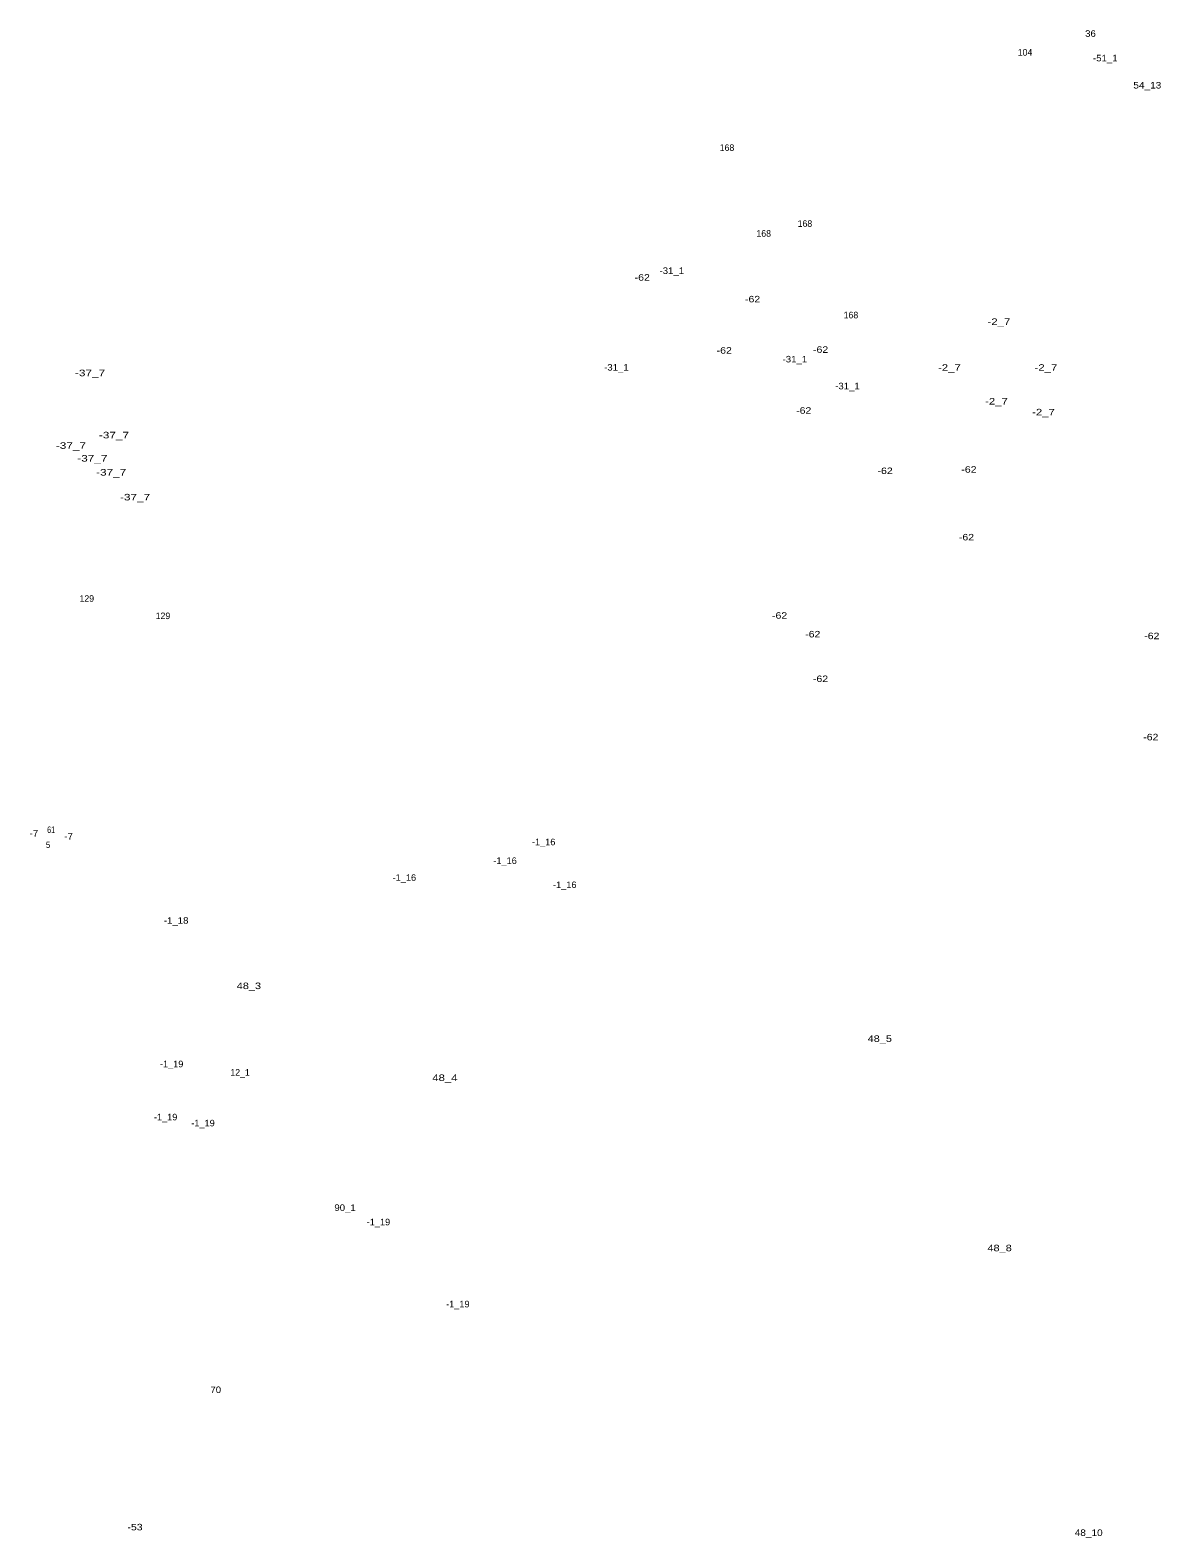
# Model space of a CAD drawing. Extents: x -660405 to -657848, y -988475 to -986360.
# Drawn here: x -659668 to -658976, y -987283 to -986360 of the extents above; entities that cross this region are included whole.
import ezdxf
from ezdxf.enums import TextEntityAlignment as Align

# ---------------------------------------------------------------- set-up
doc = ezdxf.new("R2010")
doc.units = 0
doc.header["$LTSCALE"] = 1.6
doc.layers.add('24', color=7, linetype='Continuous')

msp = doc.modelspace()

# ---------------------------------------------------------------- texts
at = {"layer": '24'}
for s, width, p in [('36', 1.1, (-659019.41, -986364.08)), ('-51_1', 1.1, (-659010.34, -986379.12)), ('54_13', 1.15, (-658984.63, -986395.73)), ('-31_1', 1.1, (-659275.63, -986509.19)), ('-62', 1.2, (-659293.71, -986513.31)), ('-62', 1.2, (-659226.19, -986526.6)), ('-2_7', 1.3, (-659075.46, -986540.37)), ('-62', 1.2, (-659243.53, -986557.97)), ('-31_1', 1.1, (-659200.319, -986563.32)), ('-62', 1.2, (-659184.57, -986557.46)), ('-37_7', 1.35, (-659631.64, -986571.75)), ('-31_1', 1.1, (-659309.54, -986568.33)), ('-2_7', 1.3, (-659105.72, -986568.42)), ('-2_7', 1.3, (-659046.68, -986568.42)), ('-31_1', 1.1, (-659168.14, -986579.77)), ('-2_7', 1.3, (-659076.94, -986589.09)), ('-62', 1.2, (-659194.9, -986594.73)), ('-2_7', 1.3, (-659048.16, -986595.73)), ('-37_7', 1.35, (-659617.02, -986609.78)), ('-37_7', 1.35, (-659643.341, -986616.18)), ('-37_7', 1.35, (-659630.231, -986623.99)), ('-62', 1.2, (-659093.8, -986630.81)), ('-37_7', 1.35, (-659618.721, -986632.58)), ('-62', 1.2, (-659145.09, -986631.64)), ('-37_7', 1.35, (-659604.091, -986647.76)), ('-62', 1.2, (-659095.28, -986672.24)), ('-62', 1.2, (-659209.66, -986720.15)), ('-62', 1.2, (-659189.36, -986731.59)), ('-62', 1.2, (-658981.87, -986732.66)), ('-62', 1.2, (-659184.6, -986758.9)), ('-62', 1.2, (-658982.48, -986794.56)), ('61', 0.8, (-659655.471, -986851.26)), ('-7', 1.1, (-659665.951, -986853.4)), ('5', 0.9, (-659657.329, -986860.48)), ('-7', 1.1, (-659644.74, -986855.25)), ('-1_16', 1.05, (-659354.061, -986858.74)), ('-1_16', 1.05, (-659377.671, -986870.18)), ('-1_16', 1.05, (-659439.291, -986880.51)), ('-1_16', 1.05, (-659341.14, -986884.94)), ('-1_18', 1.1, (-659578.959, -986906.75)), ('48_3', 1.25, (-659534.441, -986946.76)), ('48_5', 1.25, (-659148.361, -986979.08)), ('-1_19', 1.05, (-659581.721, -986994.58)), ('48_4', 1.3, (-659414.481, -987002.99)), ('-1_19', 1.05, (-659585.41, -987027.06)), ('-1_19', 1.05, (-659562.53, -987030.75)), ('90_1', 1.1, (-659475.59, -987082.48)), ('-1_19', 1.05, (-659455.16, -987091.29)), ('48_8', 1.25, (-659075.02, -987107.17)), ('-1_19', 1.05, (-659406.571, -987141.48)), ('70', 1.1, (-659554.72, -987193.92)), ('-53', 1.2, (-659604.13, -987277.95)), ('48_10', 1.15, (-659020.51, -987281.36))]:
    msp.add_text(s, height=4, dxfattribs=dict(at, width=width)).set_placement(p, align=Align.CENTER)
for s, p in [('104', (-659059.47, -986375.6)), ('168', (-659241.861, -986433.92)), ('168', (-659194.16, -986480.37)), ('168', (-659219.38, -986486.4)), ('168', (-659166, -986536.32)), ('129', (-659633.64, -986709.77)), ('129', (-659587.03, -986720.38)), ('12_1', (-659539.82, -986999.7))]:
    msp.add_text(s, height=4, dxfattribs=at).set_placement(p, align=Align.CENTER)

doc.saveas('drawing.dxf')
